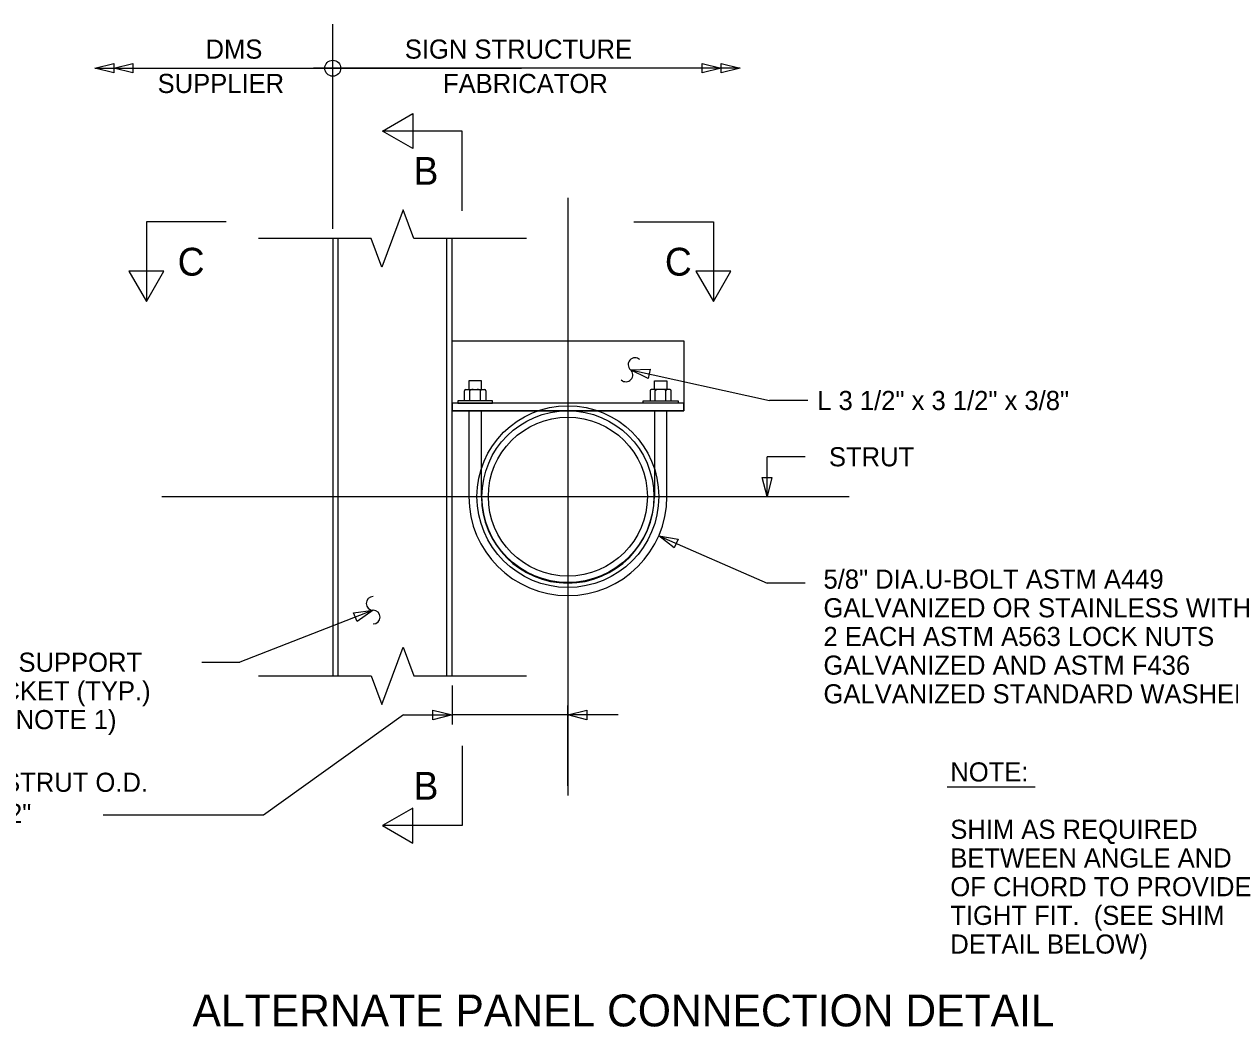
# Model space of a CAD drawing. Extents: x 3829340 to 3831660, y 499389 to 501171.
# Drawn here: x 3830616.6 to 3830805.8, y 499589.3 to 499746.6 of the extents above; entities that cross this region are included whole.
import ezdxf

# ---------------------------------------------------------------- set-up
doc = ezdxf.new("R2010")
doc.units = 0
for name, color, linetype in [('CNTR', 7, 'Continuous'), ('Default', 7, 'Continuous'), ('DIM TXT', 7, 'Continuous'), ('sign', 7, 'Continuous'), ('structure', 7, 'Continuous')]:
    doc.layers.add(name, color=color, linetype=linetype)

msp = doc.modelspace()

# ---------------------------------------------------------------- linework, layer by layer
at = {"layer": 'CNTR'}
for p, q in [((3830701.93, 499719.34), (3830701.93, 499625.6)), ((3830638.24, 499672.47), (3830746.05, 499672.47))]:
    msp.add_line(p, q, dxfattribs=at)
at = {"layer": 'Default'}
for p, q in [((3830672.83, 499729.82), (3830677.59, 499732.57)), ((3830677.59, 499732.57), (3830677.59, 499727.07)), ((3830677.59, 499727.07), (3830672.83, 499729.82)), ((3830638.57, 499707.83), (3830633.07, 499707.83)), ((3830633.07, 499707.83), (3830635.82, 499703.07)), ((3830635.82, 499703.07), (3830638.57, 499707.83)), ((3830722.01, 499707.83), (3830724.76, 499703.07)), ((3830727.51, 499707.83), (3830722.01, 499707.83)), ((3830724.76, 499703.07), (3830727.51, 499707.83)), ((3830676.16, 499638.22), (3830654.2, 499622.51)), ((3830677.59, 499623.61), (3830672.83, 499620.86)), ((3830677.59, 499618.11), (3830677.59, 499623.61)), ((3830672.83, 499620.86), (3830677.59, 499618.11))]:
    msp.add_line(p, q, dxfattribs=at)
at = {"layer": 'DIM TXT'}
for p, q in [((3830665.05, 499714.45), (3830665.05, 499746.59)), ((3830627.7, 499739.67), (3830691.63, 499739.67)), ((3830630.7, 499739.67), (3830694.63, 499739.67)), ((3830725.98, 499739.67), (3830662.05, 499739.67)), ((3830728.98, 499739.67), (3830665.05, 499739.67)), ((3830685.33, 499729.82), (3830672.83, 499729.82)), ((3830685.33, 499717.32), (3830685.33, 499729.82)), ((3830676.08, 499717.46), (3830674.41, 499712.95)), ((3830677.74, 499712.95), (3830676.08, 499717.46)), ((3830648.32, 499715.57), (3830635.82, 499715.57)), ((3830635.82, 499715.57), (3830635.82, 499703.07)), ((3830712.26, 499715.57), (3830724.76, 499715.57)), ((3830724.76, 499715.57), (3830724.76, 499703.07)), ((3830671.08, 499712.95), (3830653.4, 499712.95)), ((3830672.74, 499708.44), (3830671.08, 499712.95)), ((3830674.41, 499712.95), (3830672.74, 499708.44)), ((3830695.42, 499712.95), (3830677.74, 499712.95)), ((3830711.75, 499692.37), (3830733.55, 499687.55)), ((3830739.55, 499687.55), (3830733.55, 499687.55)), ((3830733.18, 499672.47), (3830733.18, 499678.72)), ((3830739.18, 499678.72), (3830733.18, 499678.72)), ((3830716.18, 499666.29), (3830733.18, 499658.91)), ((3830739.18, 499658.91), (3830733.18, 499658.91)), ((3830671.38, 499654.65), (3830650.49, 499646.49)), ((3830674.41, 499644.35), (3830676.08, 499648.86)), ((3830676.08, 499648.86), (3830677.74, 499644.35)), ((3830644.49, 499646.49), (3830650.49, 499646.49)), ((3830653.4, 499644.35), (3830671.08, 499644.35)), ((3830671.08, 499644.35), (3830672.74, 499639.84)), ((3830672.74, 499639.84), (3830674.41, 499644.35)), ((3830677.74, 499644.35), (3830695.42, 499644.35)), ((3830683.77, 499642.85), (3830683.77, 499636.72)), ((3830701.93, 499627.1), (3830701.93, 499639.72)), ((3830676.16, 499638.22), (3830683.77, 499638.22)), ((3830701.93, 499638.22), (3830683.77, 499638.22)), ((3830709.82, 499638.22), (3830701.93, 499638.22)), ((3830685.33, 499633.36), (3830685.33, 499620.86)), ((3830761.42, 499626.92), (3830775.23, 499626.92)), ((3830654.2, 499622.51), (3830629.05, 499622.51)), ((3830685.33, 499620.86), (3830672.83, 499620.86))]:
    msp.add_line(p, q, dxfattribs=at)
for points in [[(3830630.7, 499738.92), (3830627.7, 499739.67), (3830630.7, 499740.42)], [(3830633.7, 499738.92), (3830630.7, 499739.67), (3830633.7, 499740.42)], [(3830722.98, 499740.42), (3830725.98, 499739.67), (3830722.98, 499738.92)], [(3830725.98, 499740.42), (3830728.98, 499739.67), (3830725.98, 499738.92)], [(3830714.52, 499690.99), (3830711.75, 499692.37), (3830714.84, 499692.45)], [(3830733.93, 499675.47), (3830733.18, 499672.47), (3830732.43, 499675.47)], [(3830718.63, 499664.41), (3830716.18, 499666.29), (3830719.23, 499665.79)], [(3830668.31, 499654.25), (3830671.38, 499654.65), (3830668.86, 499652.86)], [(3830680.77, 499638.97), (3830683.77, 499638.22), (3830680.77, 499637.47)], [(3830704.93, 499637.47), (3830701.93, 499638.22), (3830704.93, 499638.97)]]:
    msp.add_lwpolyline(points, close=True, dxfattribs=at)
msp.add_circle((3830665.05, 499739.67), 1.25, dxfattribs=at)
for centre, start, end in [((3830712.47, 499693.17), 47.71, 227.71), ((3830711.03, 499691.57), 227.71, 47.71), ((3830671.38, 499655.72), 90, 270), ((3830671.38, 499653.57), 270, 90)]:
    msp.add_arc(centre, 1.08, start, end, dxfattribs=at)
at = {"layer": 'sign'}
for p, q in [((3830688.36, 499690.62), (3830686.41, 499690.62)), ((3830686.41, 499690.62), (3830686.41, 499689.27)), ((3830688.36, 499689.27), (3830688.36, 499690.62)), ((3830715.51, 499689.27), (3830715.51, 499690.62)), ((3830715.51, 499690.62), (3830717.46, 499690.62)), ((3830717.46, 499690.62), (3830717.46, 499689.27)), ((3830685.72, 499687.51), (3830685.72, 499689.08)), ((3830685.91, 499689.27), (3830688.85, 499689.27)), ((3830686.55, 499687.51), (3830686.55, 499689.08)), ((3830688.21, 499687.51), (3830688.21, 499689.08)), ((3830689.04, 499689.08), (3830689.04, 499687.51)), ((3830714.82, 499689.08), (3830714.82, 499687.51)), ((3830717.96, 499689.27), (3830715.01, 499689.27)), ((3830715.65, 499687.51), (3830715.65, 499689.08)), ((3830717.31, 499687.51), (3830717.31, 499689.08)), ((3830718.14, 499687.51), (3830718.14, 499689.08)), ((3830690.12, 499687.51), (3830684.65, 499687.51)), ((3830684.65, 499687.51), (3830684.65, 499687.12)), ((3830684.65, 499687.12), (3830690.12, 499687.12)), ((3830689.04, 499687.51), (3830685.72, 499687.51)), ((3830690.12, 499687.12), (3830690.12, 499687.51)), ((3830713.75, 499687.12), (3830713.75, 499687.51)), ((3830713.75, 499687.51), (3830719.22, 499687.51)), ((3830719.22, 499687.12), (3830713.75, 499687.12)), ((3830714.82, 499687.51), (3830718.14, 499687.51)), ((3830719.22, 499687.51), (3830719.22, 499687.12)), ((3830686.41, 499685.95), (3830686.41, 499672.47)), ((3830688.36, 499685.95), (3830686.41, 499685.95)), ((3830688.36, 499672.47), (3830688.36, 499685.95)), ((3830717.46, 499685.95), (3830715.51, 499685.95)), ((3830715.51, 499685.95), (3830715.51, 499672.47)), ((3830717.46, 499672.47), (3830717.46, 499685.95))]:
    msp.add_line(p, q, dxfattribs=at)
for centre, radius, start, end in [((3830685.91, 499689.08), 0.187, 90, 180), ((3830686.36, 499689.08), 0.187, 0, 90), ((3830688.4, 499689.08), 0.187, 90, 180), ((3830688.85, 499689.08), 0.187, 0, 90), ((3830715.01, 499689.08), 0.187, 90, 180), ((3830715.47, 499689.08), 0.187, 0, 90), ((3830717.5, 499689.08), 0.187, 90, 180), ((3830717.96, 499689.08), 0.187, 0, 90), ((3830701.93, 499672.47), 15.53, 180, 0), ((3830701.93, 499672.47), 13.57, 180, 0)]:
    msp.add_arc(centre, radius, start, end, dxfattribs=at)
for centre, major_axis, start_param, end_param in [((3830687.07, 499689.08), (-0.518, 0), 4.712389, 6.283185), ((3830687.69, 499689.08), (0.518, 0), 0, 1.570796), ((3830716.17, 499689.08), (-0.518, 0), 4.712389, 6.283185), ((3830716.8, 499689.08), (0.518, 0), 0, 1.570796)]:
    msp.add_ellipse(centre, major_axis=major_axis, ratio=0.362172, start_param=start_param, end_param=end_param, dxfattribs=at)
at = {"layer": 'structure'}
for p, q in [((3830665.05, 499712.95), (3830665.05, 499644.35)), ((3830665.86, 499712.95), (3830665.86, 499644.35)), ((3830682.96, 499644.35), (3830682.96, 499712.95)), ((3830683.77, 499644.35), (3830683.77, 499712.95)), ((3830683.77, 499696.88), (3830720.1, 499696.88)), ((3830683.77, 499685.95), (3830683.77, 499696.88)), ((3830720.1, 499696.88), (3830720.1, 499685.95)), ((3830720.1, 499687.12), (3830683.77, 499687.12)), ((3830683.77, 499687.12), (3830683.77, 499685.95)), ((3830720.1, 499685.95), (3830720.1, 499687.12)), ((3830720.1, 499685.95), (3830683.77, 499685.95)), ((3830683.77, 499685.95), (3830720.1, 499685.95))]:
    msp.add_line(p, q, dxfattribs=at)
for radius in [14.26, 13.48, 12.47]:
    msp.add_circle((3830701.93, 499672.47), radius, dxfattribs=at)

# ---------------------------------------------------------------- texts
at = {"layer": 'Default'}
msp.add_text('ALTERNATE PANEL CONNECTION DETAIL', height=4.9999, dxfattribs=at).set_placement((3830643.05, 499589.36))
at = {"layer": 'DIM TXT'}
for s, height, p in [('DMS', 3, (3830645.09, 499741.17)), ('SIGN STRUCTURE', 2.9999, (3830676.35, 499741.17)), ('SUPPLIER', 3, (3830637.57, 499735.78)), ('FABRICATOR', 3, (3830682.34, 499735.78)), ('B', 4.37, (3830677.72, 499721.38)), ('C', 4.37, (3830640.71, 499707.13)), ('C', 4.37, (3830717.15, 499707.13)), ('L 3 1/2" x 3 1/2" x 3/8"', 2.9999, (3830741.05, 499686.05)), ('  STRUT', 3, (3830740.66, 499677.22)), ('5/8" DIA.U-BOLT ASTM A449', 2.9999, (3830742.03, 499658.03)), ('GALVANIZED OR STAINLESS WITH', 2.9999, (3830742.03, 499653.53)), ('2 EACH ASTM A563 LOCK NUTS', 2.9999, (3830742.03, 499649.03)), ('SIGN SUPPORT', 2.9999, (3830604.82, 499644.99)), ('GALVANIZED AND ASTM F436', 2.9999, (3830742.03, 499644.53)), ('BRACKET (TYP.)', 2.9999, (3830604.82, 499640.49)), ('GALVANIZED STANDARD WASHERS', 2.9999, (3830742.03, 499640.03)), ('(SEE NOTE 1)', 2.9999, (3830604.82, 499635.99)), ('NOTE:', 3, (3830761.93, 499627.78)), ('1/2 x STRUT O.D.', 2.9999, (3830603.52, 499626.16)), ('B', 4.37, (3830677.72, 499624.92)), ('+ 1 1/2"', 3, (3830603.95, 499621.26)), ('SHIM AS REQUIRED ', 2.9999, (3830761.93, 499618.78)), ('BETWEEN ANGLE AND TOP ', 2.9999, (3830761.93, 499614.28)), ('OF CHORD TO PROVIDE ', 2.9999, (3830761.93, 499609.78)), ('TIGHT FIT.  (SEE SHIM ', 2.9999, (3830761.93, 499605.28)), ('DETAIL BELOW) ', 2.9999, (3830761.93, 499600.78))]:
    msp.add_text(s, height=height, dxfattribs=at).set_placement(p)

doc.saveas('drawing.dxf')
